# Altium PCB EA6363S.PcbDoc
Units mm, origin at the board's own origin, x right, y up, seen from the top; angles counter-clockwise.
Board outline 105 x 77 mm, 2 copper layers (Top Layer, Bottom Layer); 55 components, 33 nets, 127 pads, 0 vias.
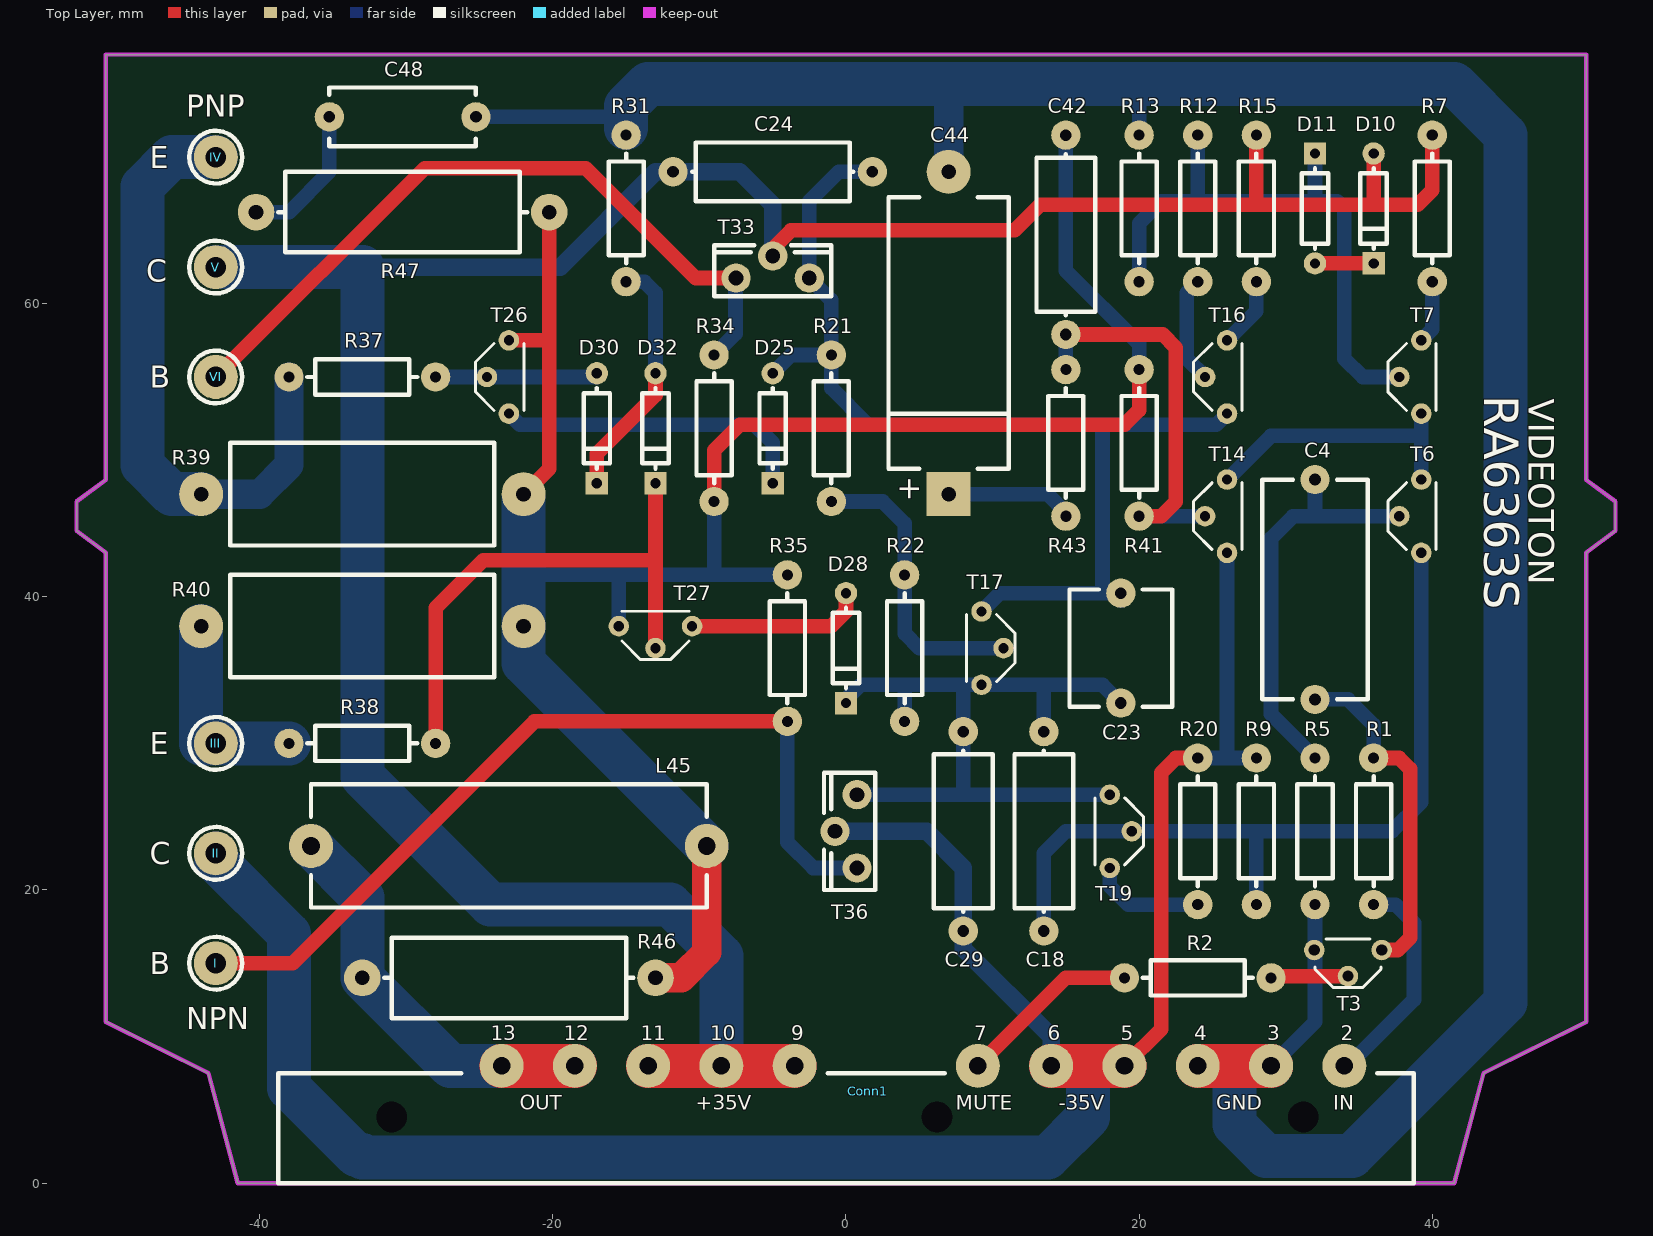
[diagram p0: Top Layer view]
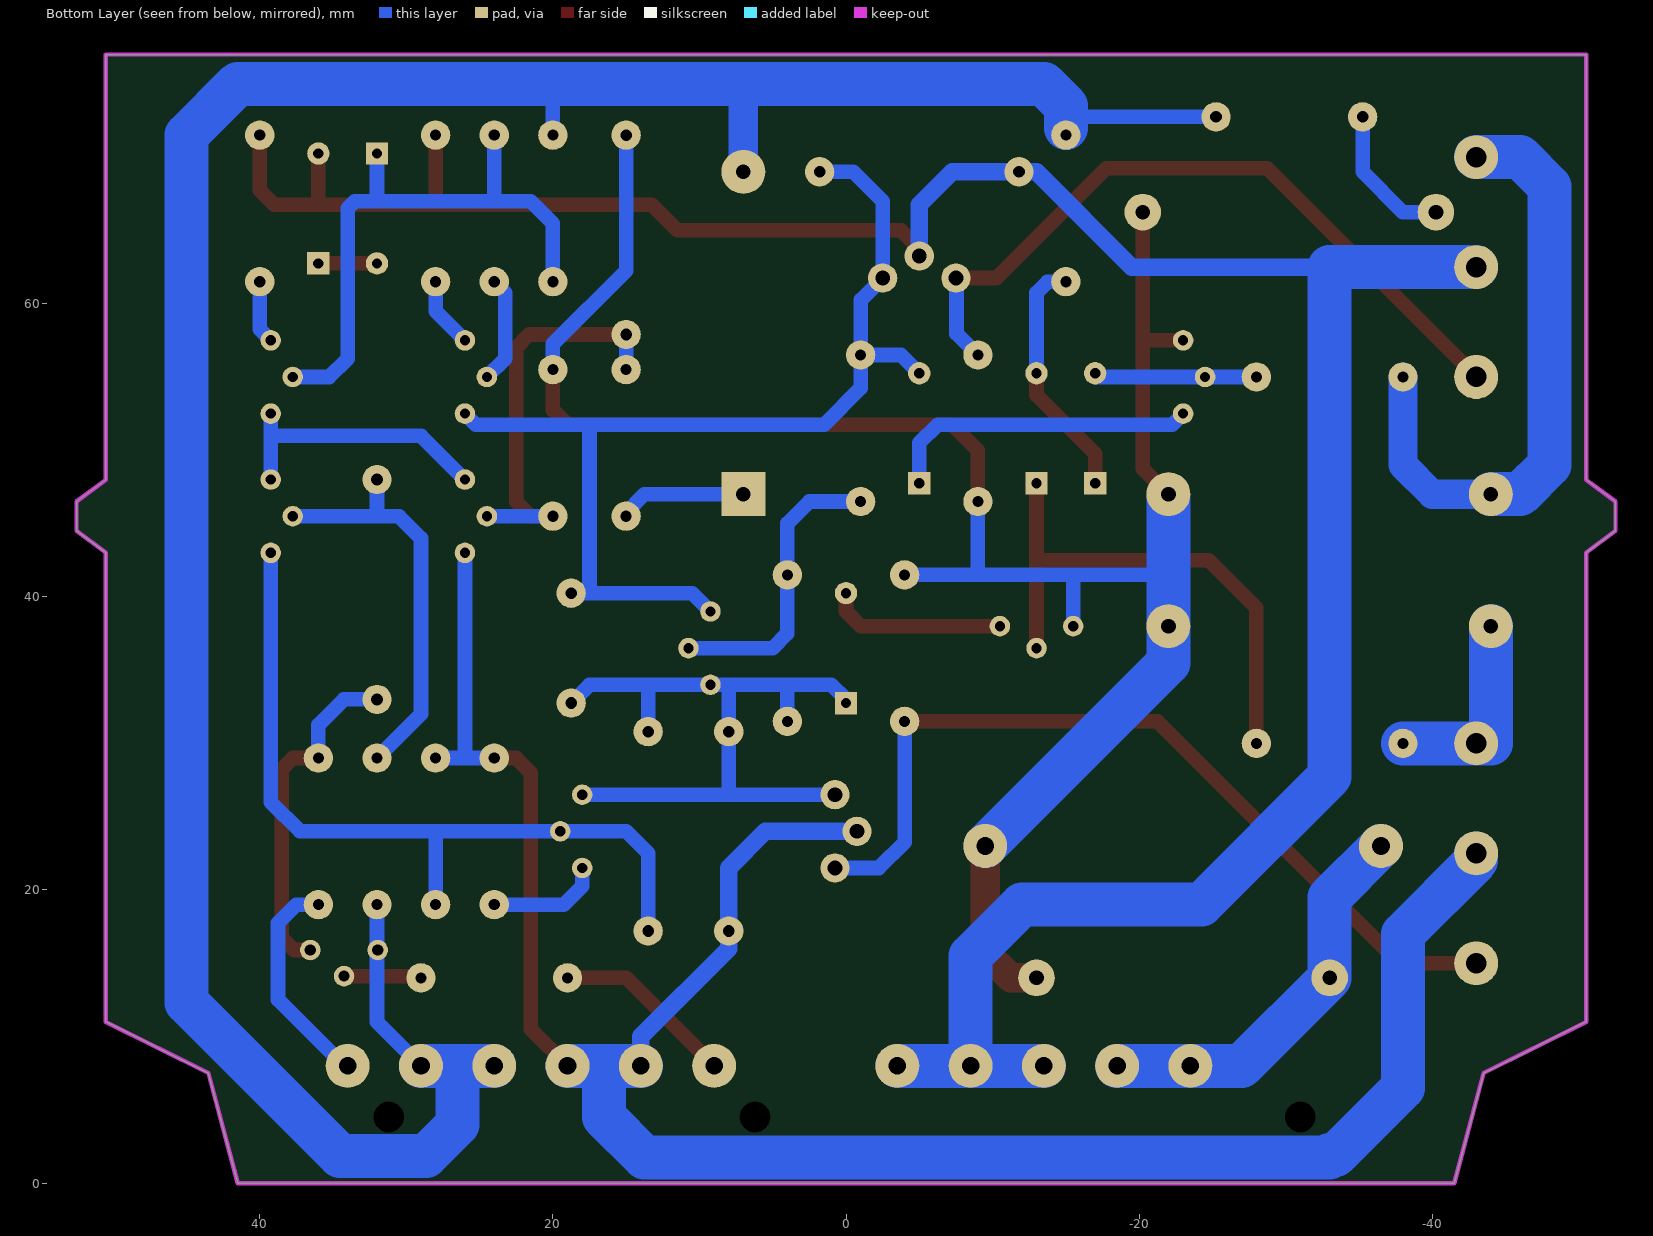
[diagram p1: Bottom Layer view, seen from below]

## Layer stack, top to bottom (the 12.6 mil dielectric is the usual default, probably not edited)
Top Solder: solder mask 0.0102, Solder Resist, Dk 3.5
Top Layer: signal copper 0.0356
Dielectric 1: dielectric 0.32, FR-4, Dk 4.8
Bottom Layer: signal copper 0.0356
Bottom Solder: solder mask 0.0102, Solder Resist, Dk 3.5

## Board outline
-50.5,43 -52.5,44.5 -52.5,46.5 -50.5,48 -50.5,77 50.5,77 50.5,48 52.5,46.5 52.5,44.5 50.5,43 50.5,11 43.5,7.5 41.5,0 -41.5,0 -43.5,7.5 -50.5,11

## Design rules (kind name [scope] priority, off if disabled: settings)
Clearance [All] p1: gap=0.1
PolygonConnect [All] p1: connectstyle=Relief reliefconductorwidth=0.254 reliefentries=4 polygonreliefangle="90 Angle" airgapwidth=0.254
RoutingVias [All] p1: holewidth=0.711 width=1.27 viastyle="Through Hole" minholewidth=0.711 minwidth=1.27 maxholewidth=0.711 maxwidth=1.27
SolderMaskExpansion [All] p1: expansion=0.102
Width [All] p1: maxlimit=4 minlimit=0.8 preferedwidth=1
30 further rules are at their usual default settings.

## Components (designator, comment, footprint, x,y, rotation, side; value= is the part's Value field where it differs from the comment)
C4 "4u7" "C2334 100V" 32,40.5 r90 top
C18 "22p" C2441 13.5,24 r90 top locked
C23 "100n" "C2332 400V" 18.75,36.5 r90 top locked
C24 "56p" C2441 -5,69 r180 top
C29 "56p" C2441 8,24 r90 top locked
C42 "10p" C2441 15,64.7 r90 top
C44 "47u" "021 ASM Wishay" 7,58 r90 top locked
C48 "150n" "C2333 250V" -30.25,72.75 r180 top
Conn1 "Videoton connector" "Videoton connector" 0,8 r0 top locked
D10 "4148" "DO-35 3R" 36,66.5 r270 top
D11 "4148" "DO-35 3R" 32,66.5 r90 top
D25 "4148" "DO-35 3R" -5,51.5 r270 top
D28 "4148" "DO-35 3R" 0,36.5 r270 top
D30 "4148" "DO-35 3R" -17,51.5 r270 top
D32 "4148" "DO-35 3R" -13,51.5 r270 top
I "1pin" "1pin 1.4x3" -43,15 r90 top locked
II "1pin" "1pin 1.4x3" -43,22.5 r0 top locked
III "1pin" "1pin 1.4x3" -43,30 r0 top locked
IV "1pin" "1pin 1.4x3" -43,70 r0 top locked
L45 "2uH" "2.2 uH" -23,23 r0 top
R1 "8k2" MF0207 36,24 r270 top
R2 "4k7" MF0207 24,14 r180 top
R5 "82k" MF0207 32,24 r270 top
R7 "470R" MF0207 40,66.5 r270 top
R9 "1k8" MF0207 28,24 r90 top
R12 "470R" MF0207 24,66.5 r270 top
R13 "8k2" MF0207 20,66.5 r90 top
R15 "100R" MF0207 28,66.5 r270 top
R20 "68R" MF0207 24,24 r90 top
R21 "3k3" MF0207 -1,51.5 r270 top
R22 "1k5" MF0207 4,36.5 r270 top
R31 "1k" MF0207 -15,66.5 r270 top
R34 "82R" MF0207 -9,51.5 r270 top
R35 "82R" MF0207 -4,36.5 r270 top
R37 "150R" MF0207 -33,55 r180 top
R38 "150R" MF0207 -33,30 r180 top
R39 "0R47" KNP5WS -33,47 r180 top locked
R40 "0R47" KNP5WS -33,38 r0 top
R41 "82k" MF0207 20,50.5 r90 top
R43 "2k7" MF0207 15,50.5 r90 top
R46 "4R7" MOR03 -23,14 r0 top locked
R47 "4R7" MOR03 -30.25,66.25 r0 top
T3 "BF244A" TO-92 34.25,15 r0 top
T6 "BC213B" BC557 39.25,45.5 r270 top
T7 "BC327-25" BC557 39.25,55 r270 top
T14 "BC213B" BC557 26,45.5 r270 top
T16 "BC327-25" BC557 26,55 r270 top
T17 "BC327-25" BC547 9.25,36.5 r90 top
T19 "BC546B" BC547 18,24 r90 top
T26 "BC337-25" BC547 -23,55 r270 top
T27 "BC327-25" BC557 -13,38 r0 top
T33 "BD139" BD139 -5,62.25 r0 top locked
T36 "BD140" BD139 0.25,24 r90 top
V "1pin" "1pin 1.4x3" -43,62.5 r90 top locked
VI "1pin" "1pin 1.4x3" -43,55 r0 top locked

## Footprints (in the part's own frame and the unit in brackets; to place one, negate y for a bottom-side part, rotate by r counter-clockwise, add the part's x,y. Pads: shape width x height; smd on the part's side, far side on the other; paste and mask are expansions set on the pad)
"1pin 1.4x3" [mm]
  round 3 hole 1.4: 1(0,0)
  silkscreen extent -1.8,-1.8 1.8,1.8
"2.2 uH" [mm] "inductor"
  round 3 hole 1.2: 1(-13.5,0) 2(13.5,0)
  silkscreen extent -13.5,-4.2 13.5,4.2, body extent -13.5,-4.15 13.5,4.25, height 9.7
"021 ASM Wishay" [mm]
  rect 3x3 hole 1: 1(-11,0)
  round 3 hole 1: 2(11,0)
  silkscreen extent -9.25,-4.1 9.25,4.1, body extent -9.25,-4.2 9.25,4.2, height 9.2
BC547 [mm]
  round 1.4 hole 0.7: B(0,-1.5) C(2.5,0) E(-2.5,0)
  silkscreen extent -2.29,-2.29 2.29,1.02, body extent -2.3,-2.3 2.3,1, height 9.3
BC557 [mm]
  round 1.4 hole 0.7: B(0,-1.5) C(2.5,0) E(-2.5,0)
  silkscreen extent -2.29,-2.29 2.29,1.02, body extent -2.3,-2.3 2.3,1, height 9.3
BD139 [mm]
  round 2 hole 1: B(2.5,-0.5) C(0,1) E(-2.5,-0.5)
  silkscreen extent -4,-1.75 4,1.75, body extent -4,-1.75 4,1.75, height 15
"C2332 400V" [mm]
  round 2 hole 0.8: 1(-3.75,0) 2(3.75,0)
  silkscreen extent -4,-3.5 4,3.5, body extent -4,-3.5 4,3.5, height 8.6
"C2333 250V" [mm]
  round 2 hole 0.8: 1(-5,0) 2(5,0)
  silkscreen extent -5,-2 5,2, body extent -5,-2 5,2, height 6.8
"C2334 100V" [mm] "4u7"
  round 2 hole 0.8: 1(-7.5,0) 2(7.5,0)
  silkscreen extent -7.5,-3.6 7.5,3.6, body extent -7.5,-3.6 7.5,3.6, height 10.2
C2441 [mm]
  round 2 hole 0.8: 1(-6.8,0) 2(6.8,0)
  silkscreen extent -5.5,-2 5.5,2, body extent -5.25,-2 5.35,2, height 4.5
"DO-35 3R" [mm]
  round 1.524 hole 0.7: A(-3.75,0)
  rect 1.524x1.524 hole 0.7: K(3.75,0)
  silkscreen extent -2.75,-0.9 2.75,0.9, body extent -2.5,-1.1 2.5,1.1, height 2.5
KNP5WS [mm]
  round 3 hole 1: 1(-11,0) 2(11,0)
  silkscreen extent -9,-3.5 9,3.5, body extent -9,-3.5 9,3.5, height 7.5
MF0207 [mm]
  round 2 hole 0.762: 1(-5,0) 2(5,0)
  silkscreen extent -3.75,-1.2 3.75,1.2, body extent -3.4,-1.27 3.4,1.27, height 2.77
MOR03 [mm] "3W resistor"
  round 2.5 hole 1: 1(-10,0) 2(10,0)
  silkscreen extent -8.5,-2.75 8.5,2.75, body extent -8,-2.75 8,2.75, height 5.75
TO-92 [mm]
  round 1.4 hole 0.762: D(2.3,0.9) G(0,-0.881) S(-2.3,0.9)
  silkscreen extent -2.25,-1.64 2.25,1.66, body extent -2.3,-1.7 2.3,1.7, height 9.3
"Videoton connector" [mm]
  round 3 hole 1.2: 2(34,0) 3(29,0) 4(24,0) 5(19,0) 6(14,0) 7(9,0) 9(-3.5,0) 10(-8.5,0) 11(-13.5,0) 12(-18.5,0) 13(-23.5,0)
  round 0 hole 2.1: 16(31.2,-3.5) 17(6.2,-3.5) 18(-31,-3.5)
  silkscreen extent -38.75,-8 38.75,-0.5, body extent -38.75,-8 38.75,-0.5, height 8

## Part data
C4 C18 C23 C24 C29 C42 C48: library part CAP
C44: library part "CAP POL"
D10 D11 D25 D28 D30 D32: library part Dioda
L45: library part Inductor_1
R1 R2 R5 R7 R9 R12 R13 R15 R20 R21 R22 R31 R34 R35 R37 R38 R39 R40 R41 R43 R46 R47: library part RES_THT
T3: library part JFET-N
T6 T7 T14 T16 T27 T36: library part PNP
T17 T19 T26 T33: library part NPN

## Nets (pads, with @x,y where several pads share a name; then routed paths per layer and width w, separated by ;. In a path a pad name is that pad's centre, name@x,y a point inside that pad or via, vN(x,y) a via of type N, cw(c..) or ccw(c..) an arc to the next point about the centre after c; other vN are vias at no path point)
2: Conn1.2 R1.2 | length 15.1
  Bottom Layer w1: Conn1.2 34.25,8 38.75,12.5 38.75,17.75 37.5,19 R1.2
3: C44.2 C48.1 Conn1.3 Conn1.4 R5.2 R13.2 R31.1 T3.S | length 193
  Top Layer w3: Conn1.4 Conn1.3
  Bottom Layer w1: C48.1 -16.25,72.75 R31.1 ; R13.2 20,75 ; Conn1.3 32,11 R5.2
  Bottom Layer w2: C44.2 7,75
  Bottom Layer w3: R31.1@-15,72 -15,73.5 -13.5,75 7,75 20,75 41.5,75 45,71.5 45,12.336 34.514,1.85 28.65,1.85 26.5,4 26.5,8 ; Conn1.4 26.5,8 ; Conn1.3 26.5,8
5: C29.1 Conn1.5 Conn1.6 II.1 R9.2 R20.2 T14.C T36.C | length 156.8
  Top Layer w1: Conn1.5 21.5,10.5 21.5,28 22.5,29 R20.2
  Top Layer w3: Conn1.6 Conn1.5
  Bottom Layer w1: R20.2 R9.2 ; 26,29 T14.C
  Bottom Layer w1.2: T36.C 5.5,24 8,21.5 C29.1 8,16 14,10 Conn1.6
  Bottom Layer w3: II.1 -43,22 -38,17 -38,6.5 -33.404,1.904 -33,1.904 ; -33,1.75 13.75,1.75 16.5,4.5 16.5,8 ; Conn1.6 16.5,8 ; Conn1.5 16.5,8
7: Conn1.7 R2.2 | length 12.6
  Top Layer w1: Conn1.7 15,14 R2.2@18.887,14 ; R2.2 R2.2@18.887,14 ; R2.2@19,14.113 R2.2@18.887,14
9: C24.2 Conn1.9 Conn1.10 Conn1.11 D10.A R7.1 R15.1 T33.C V.1 | length 196.1
  Top Layer w1: T33.C -5,63.75 -3.75,65 11.5,65 13.25,66.75 28,66.75 ; R15.1 28,66.75 ; D10.A 36,66.75 ; R7.1 40,67.75 39,66.75 36,66.75 ; 28,66.75 36,66.75
  Top Layer w3: Conn1.11 Conn1.10 Conn1.9
  Bottom Layer w1.2: -33,62.5 -19.5,62.5 -13,69 C24.2 -7.25,69 -5,66.75 T33.C
  Bottom Layer w3: V.1 -33,62.5 -33,27.75 -24.25,19 -12,19 -8.5,15.5 Conn1.10 ; Conn1.11 Conn1.10 ; Conn1.9 Conn1.10
12: Conn1.12 Conn1.13 L45.1 R46.1 | length 32.4
  Top Layer w3: Conn1.13 Conn1.12
  Bottom Layer w3: L45.1 -33,19.5 R46.1 -27,8 Conn1.13 Conn1.12
NetC4_1: C4.1 R1.1 T3.D | length 23.8
  Top Layer w1: R1.1 37.75,29 38.5,28.25 38.5,16.75 37.65,15.9 T3.D
  Bottom Layer w1: C4.1 34.25,33 36,31.25 R1.1 R1.1@35.75,29
NetC4_2: C4.2 R5.1 T6.B | length 28.1
  Bottom Layer w1: R5.1 29,32 29,44 30.5,45.5 32,45.5 ; C4.2 32,45.5 ; T6.B 32,45.5
NetC18_1: C18.1 R9.1 T6.C T19.B | length 54.5
  Bottom Layer w1: C18.1 13.5,22.5 15,24 T19.B 28,24 ; R9.1 28,24 ; T6.C 39.25,26 37.25,24 28,24
NetC18_2: C18.2 C23.1 C29.2 D28.K R22.2 T17.E T19.C T36.B | length 50.4
  Bottom Layer w1: D28.K 0,33 1,34 4,34 ; T36.B 8,26.5 ; R22.2 4,34 ; C18.2 13.5,34 ; T19.C 13,26.5 8,26.5 ; C23.1 17.5,34 13.5,34 ; 4,34 8,34 ; 8,26.5 8,34 ; 8,34 13.5,34
NetC23_2: C23.2 C24.1 D25.A R21.1 T16.C T17.C T33.B | length 74.1
  Bottom Layer w1: D25.A -3.75,56.5 R21.1 ; C24.1 -0.5,69 -2.5,67 T33.B -1,60.25 R21.1 ; T17.C 10.5,40.25 C23.2 18.75,39.75 C23.2@18.25,40.25 ; 17.5,40.25 17.5,51.75 ; T16.C 25.25,51.75 17.5,51.75 ; R21.1 -1,54.25 1.5,51.75 17.5,51.75
NetC42_1: C42.1 R41.1 R43.2 T14.B | length 28.5
  Top Layer w1: C42.1 21.6,57.9 22.5,57 22.5,46.5 21.5,45.5 R41.1
  Bottom Layer w1: R43.2 C42.1 C42.1@15,58.25 ; R41.1 T14.B
NetC42_2: C42.2 L45.2 R34.2 R35.1 R39.1 R40.2 R41.2 R46.2 R47.2 T26.E T27.E | length 144.1
  Top Layer w1: T26.E -20.25,57.5 ; R39.1 -20.25,48.75 -20.25,57.5 ; R47.2 -20.25,57.5 ; R34.2 -9,50 -7.25,51.75 19,51.75 20,52.75 R41.2
  Top Layer w2: R46.2 -11.25,14 -9.5,15.75 L45.2
  Bottom Layer w1: -22.25,41.5 -9,41.5 ; T27.E -15.5,41.5 ; R34.2 -9,41.5 ; R35.1 -9,41.5 ; C42.2@15,71.3 15,62.25 20,57.25 R41.2
  Bottom Layer w3: R39.1@-22,46.75 R40.2 -22,35.5 L45.2
NetC44_1: C44.1 R43.1 | length 9.2
  Bottom Layer w1: C44.1@7,48 8,47 13.75,47 15,45.75 R43.1
NetC48_2: C48.2 R47.1 | length 9.6
  Bottom Layer w1: R47.1 -38,66.25 -35.25,69 C48.2@-35.25,72.5
NetD10_K: D10.K D11.A | length 3.5
  Top Layer w1: D11.A D10.K@35.5,62.75
NetD11_K: D11.K R12.1 R13.1 T7.B | length 41.1
  Bottom Layer w1: R13.1 20,65.5 21.5,67 24,67 ; R12.1 24,67 ; D11.K 32,67 ; T7.B 35.25,55 34,56.25 34,66.5 33.5,67 32,67 ; 24,67 32,67
NetD25_K: D25.K T26.C | length 21.6
  Bottom Layer w1: T26.C -22.25,51.75 -6.25,51.75 -5,50.5 D25.K
NetD28_A: D28.A T27.C | length 12.2
  Top Layer w1: T27.C -1,38 0,39 D28.A
NetD30_A: D30.A R37.1 T26.B | length 11
  Bottom Layer w1: R37.1 -22.25,55 D30.A@-17,55
NetD30_K: D30.K D32.A R31.2 | length 17
  Top Layer w1: D30.K -17,49.75 -13,53.75 D32.A
  Bottom Layer w1: R31.2 -13.75,61.5 -13,60.75 D32.A
NetD32_K: D32.K R38.1 T27.B | length 36.8
  Top Layer w1: R38.1 -28,39.25 -24.75,42.5 -13,42.5 ; T27.B D32.K
NetI_1: I.1 R35.2 T36.E | length 60.1
  Top Layer w1: I.1 -37.75,15 -21.25,31.5 R35.2 R35.2@-3.5,31.5
  Bottom Layer w1: R35.2 -4,23.25 -2.25,21.5 T36.E
NetIII_1: III.1 R38.2 R40.1 | length 14
  Bottom Layer w3: R40.1 -44,30 R38.2
NetIV_1: IV.1 R37.2 R39.2 | length 41.5
  Bottom Layer w2: R39.2@-43,47 -40,47 -38,49 R37.2
  Bottom Layer w3: R39.2 -46,47 -48,49 -48,68 -46,70 IV.1
NetR2_1: R2.1 T3.G | length 5
  Top Layer w1: R2.1@29,14.113 33.994,14.113 T3.G@34,14.119
NetR7_2: R7.2 T7.E | length 4.3
  Bottom Layer w1: T7.E 40,58.25 R7.2
NetR12_2: R12.2 T16.B | length 7.3
  Bottom Layer w1: R12.2 23.25,60.75 23.25,56.25 T16.B
NetR15_2: R15.2 T16.E | length 4.8
  Bottom Layer w1: T16.E 28,59.5 R15.2
NetR20_1: R20.1 T19.E | length 7.8
  Bottom Layer w1: T19.E 18,20.25 19.25,19 R20.1
NetR21_2: R21.2 R22.1 T17.B | length 19.8
  Bottom Layer w1: R21.2@-0.5,46.5 2.5,46.5 4,45 R22.1 4,37.5 5,36.5 T17.B
NetR34_1: R34.1 T33.E VI.1 | length 50.4
  Top Layer w1: VI.1 -28.75,69.25 -17.75,69.25 -10.25,61.75 T33.E
  Bottom Layer w1: R34.1 -7.54,57.96 T33.E@-7.54,61.75
NetT6_E: T6.E T7.C T14.E | length 19
  Bottom Layer w1: T14.E 29,51 39.25,51 ; T6.E T7.C
pads on no net: Conn1.16 Conn1.17 Conn1.18

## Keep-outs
Keep-Out Layer:
  lines w0.3: -52.5,44.5 -50.5,43 -50.5,11 -43.5,7.5 -41.5,0 41.5,0 43.5,7.5 50.5,11 50.5,43 52.5,44.5 52.5,46.5 50.5,48 50.5,77 -50.5,77 -50.5,71.5 -50.5,48 -52.5,46.5 -52.5,44.5

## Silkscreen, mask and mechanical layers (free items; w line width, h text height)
Top Overlay:
  text "PNP" at -45,72.75 h1.5
  text "E" at -47.5,69.25 h1.5
  text "C" at -47.75,61.5 h1.5
  text "B" at -47.5,54.25 h1.5
  text "RA6363S" at 42.75,53.75 h4 r270
  text "VIDEOTON" at 46,53.5 h3 r270
  text "E" at -47.5,29.25 h1.5
  text "C" at -47.5,21.75 h1.5
  text "B" at -47.5,14.25 h1.5
  text "NPN" at -45,10.5 h1.5
  text "13" at -24.25,9.75 h1
  text "12" at -19.25,9.75 h1
  text "11" at -14,9.75 h1
  text "10" at -9.25,9.75 h1
  text "9" at -3.75,9.75 h1
  text "7" at 8.75,9.75 h1
  text "6" at 13.75,9.75 h1
  text "5" at 18.75,9.75 h1
  text "4" at 23.75,9.75 h1
  text "3" at 28.75,9.75 h1
  text "2" at 33.75,9.75 h1
  text "OUT" at -22.25,5 h1
  text "+35V" at -10.25,5 h1
  text "MUTE" at 7.5,5 h1
  text "-35V" at 14.5,5 h1
  text "GND" at 25.25,5 h1
  text "IN" at 33.25,5 h1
